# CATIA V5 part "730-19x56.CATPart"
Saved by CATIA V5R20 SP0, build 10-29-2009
Part number: 730-19x56
Definition: NONE
Nomenclature: 730-19x56
Source: Unknown
Description: 730-19x56
Bounding box of the stored display mesh (mm): x -12.441 to 12.441, y -11.818 to 11.818, z 0 to 56
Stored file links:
  C:\Users\Utente\Desktop\IO LAVORO\3D X SITO CF\X SITO\730\730-19x56.CATPart
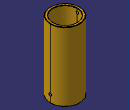
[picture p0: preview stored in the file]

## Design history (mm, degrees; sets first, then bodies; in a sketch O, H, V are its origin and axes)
Body1 "730-19x56" (main body)
  Solid1: solid without history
